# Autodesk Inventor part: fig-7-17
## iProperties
Created: 2004-05
Part Number: fig-7-17
Document SubType Name: Modeling
Designer: CADCIM Technologies
Manufacturer: Standard
Standards Organization: Custom
Density: 1 g/cm^3
Author: CADCIM Technologies
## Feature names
1. Extrusion1
